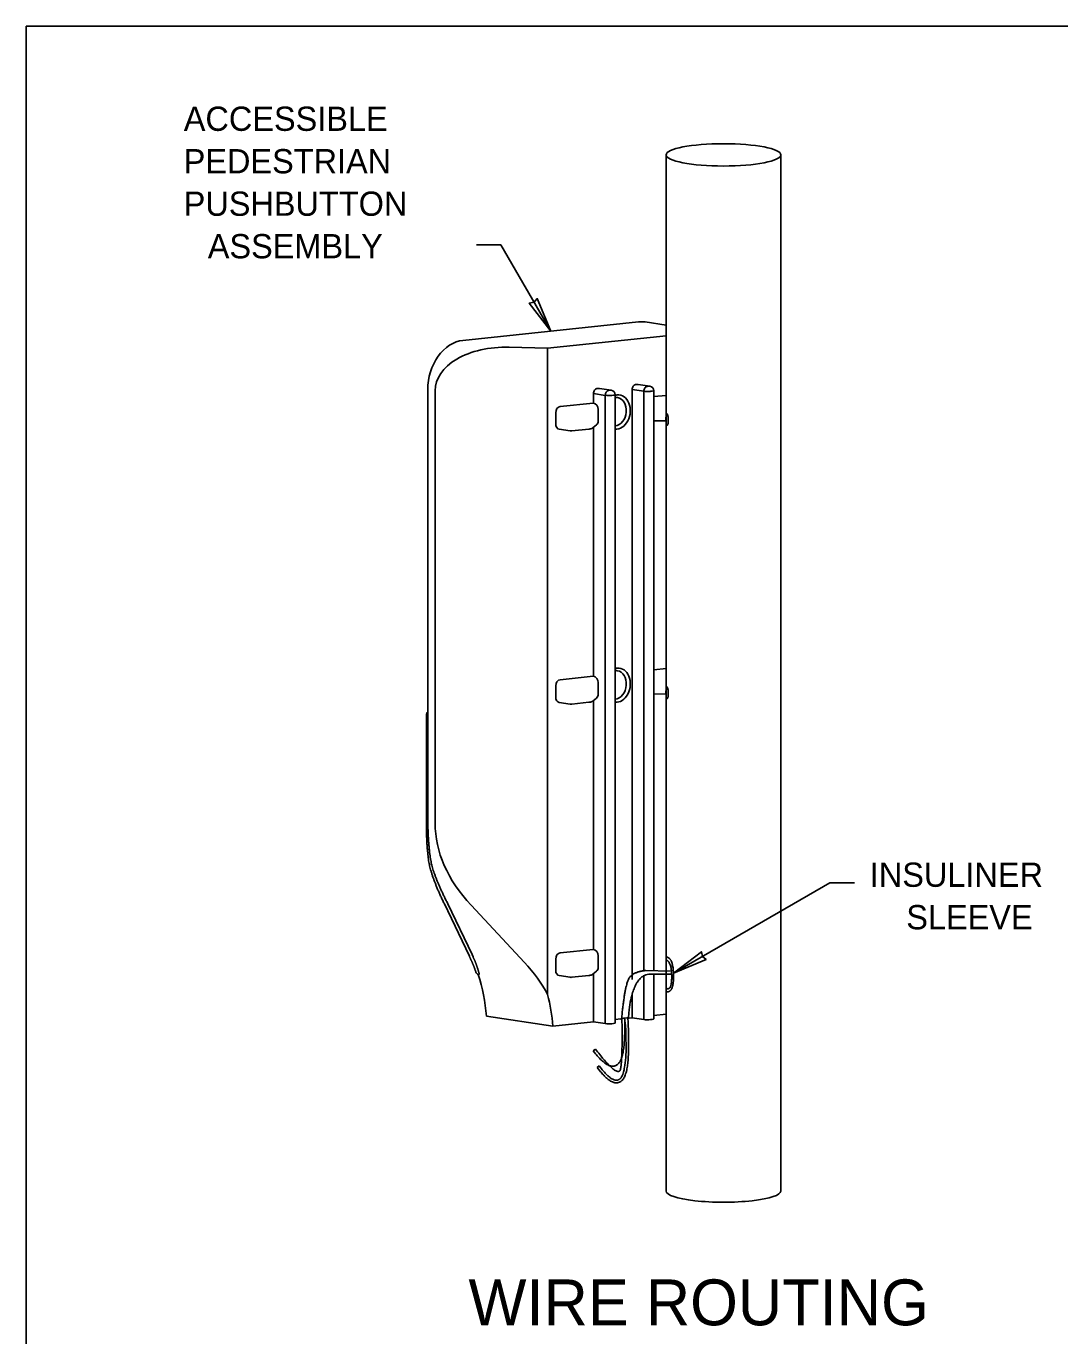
# Model space of a CAD drawing. Extents: x 2815109 to 2818234, y 992846 to 994883.
# Drawn here: x 2815109 to 2815718, y 994113 to 994883 of the extents above; entities that cross this region are included whole.
import ezdxf

# ---------------------------------------------------------------- set-up
doc = ezdxf.new("R2010")
doc.units = 0
for name, color, linetype in [('Common-Dimensions', 7, 'Continuous'), ('Common-Notes', 7, 'Continuous'), ('Draft_Named_Boundary', 7, 'Continuous'), ('Level 18', 7, 'Continuous'), ('Level 31', 7, 'Continuous'), ('Level 33', 7, 'Continuous'), ('Level 42', 7, 'Continuous')]:
    doc.layers.add(name, color=color, linetype=linetype)

msp = doc.modelspace()

# ---------------------------------------------------------------- linework, layer by layer
at = {"layer": 'Common-Dimensions'}
for p, q in [((2815374.39, 994754.77), (2815388.79, 994754.77)), ((2815418.04, 994704.1), (2815388.79, 994754.77)), ((2815490.29, 994326.38), (2815582.26, 994379.48)), ((2815596.66, 994379.48), (2815582.26, 994379.48))]:
    msp.add_line(p, q, dxfattribs=at)
for points in [[(2815418.04, 994704.1), (2815405.44, 994720.55), (2815408.24, 994721.07), (2815410.09, 994723.24)], [(2815490.29, 994326.38), (2815509.43, 994334.33), (2815507.26, 994336.18), (2815506.74, 994338.98)]]:
    msp.add_lwpolyline(points, close=True, dxfattribs=at)
at = {"layer": 'Draft_Named_Boundary'}
msp.add_lwpolyline([(2815109.48, 992845.97), (2818234.48, 992845.97), (2818234.48, 994883.47), (2815109.48, 994883.47)], close=True, dxfattribs=at)
at = {"layer": 'Level 18'}
for p, q in [((2815474.03, 994327.88), (2815488.4, 994327.61)), ((2815475.73, 994325.67), (2815488.52, 994325.67)), ((2815444.4, 994281.62), (2815443.11, 994280.63)), ((2815446.55, 994271.79), (2815445.35, 994270.87))]:
    msp.add_line(p, q, dxfattribs=at)
msp.add_ellipse((2815461.77, 994299.66), major_axis=(-2.42, -0.31), ratio=0.103975, start_param=2.35204, end_param=6.98667, dxfattribs=at)
for points, degree in [([(2815459.75, 994299.54), (2815461.29, 994315.63), (2815465.2, 994327.28), (2815474.03, 994327.88)], 2), ([(2815463.71, 994300.06), (2815464.04, 994304.36), (2815464.51, 994307.63), (2815465.79, 994313.65), (2815466.62, 994316.35), (2815468.13, 994319.67), (2815468.68, 994320.66), (2815469.86, 994322.36), (2815470.49, 994323.08), (2815471.82, 994324.25), (2815472.53, 994324.71), (2815474.03, 994325.38), (2815474.84, 994325.59), (2815475.73, 994325.67)], 3), ([(2815443.11, 994280.63), (2815444.25, 994279.14), (2815445.32, 994277.84), (2815447.35, 994275.62), (2815448.3, 994274.7), (2815450.12, 994273.21), (2815450.99, 994272.63), (2815452.3, 994272.02), (2815452.73, 994271.86), (2815453.61, 994271.65), (2815454.05, 994271.59), (2815454.94, 994271.6), (2815455.38, 994271.67), (2815456.22, 994271.93), (2815456.61, 994272.12), (2815457.33, 994272.6), (2815457.65, 994272.89), (2815458.23, 994273.52), (2815458.49, 994273.87), (2815459.19, 994275), (2815459.56, 994275.86), (2815460.19, 994277.78), (2815460.44, 994278.85), (2815461.08, 994282.36), (2815461.34, 994285.11), (2815461.61, 994291.33), (2815461.63, 994294.79), (2815461.56, 994298.81), (2815461.56, 994299.1), (2815461.55, 994299.38)], 3), ([(2815444.4, 994281.62), (2815457.92, 994263.9), (2815460.34, 994276.37), (2815459.94, 994299.59)], 2), ([(2815445.35, 994270.87), (2815446.5, 994269.38), (2815447.57, 994268.08), (2815449.59, 994265.86), (2815450.54, 994264.94), (2815452.37, 994263.45), (2815453.24, 994262.87), (2815454.54, 994262.26), (2815454.98, 994262.1), (2815455.86, 994261.89), (2815456.3, 994261.83), (2815457.19, 994261.84), (2815457.63, 994261.91), (2815458.46, 994262.17), (2815458.86, 994262.36), (2815459.58, 994262.84), (2815459.9, 994263.12), (2815460.48, 994263.76), (2815460.74, 994264.11), (2815461.44, 994265.24), (2815461.81, 994266.1), (2815462.44, 994268.02), (2815462.69, 994269.09), (2815463.33, 994272.59), (2815463.58, 994275.35), (2815463.86, 994281.57), (2815463.87, 994285.03), (2815463.76, 994292.17), (2815463.64, 994295.8), (2815463.48, 994300.06)], 3), ([(2815446.55, 994271.79), (2815447.68, 994270.32), (2815448.72, 994269.06), (2815450.67, 994266.92), (2815451.57, 994266.05), (2815453.26, 994264.67), (2815454.03, 994264.17), (2815455.1, 994263.67), (2815455.45, 994263.54), (2815456.11, 994263.38), (2815456.43, 994263.34), (2815457.03, 994263.35), (2815457.32, 994263.4), (2815457.87, 994263.57), (2815458.13, 994263.69), (2815458.62, 994264.02), (2815458.86, 994264.22), (2815459.29, 994264.7), (2815459.49, 994264.97), (2815460.07, 994265.9), (2815460.4, 994266.65), (2815460.97, 994268.41), (2815461.21, 994269.41), (2815462.23, 994275), (2815462.42, 994281.31), (2815462.25, 994291.86), (2815462.15, 994295.17), (2815461.48, 994299.88)], 3)]:
    msp.add_open_spline(points, degree=degree, dxfattribs=at)
at = {"layer": 'Level 31'}
for p, q in [((2815485.92, 994807.77), (2815485.92, 994295.55)), ((2815553.42, 994198.16), (2815553.42, 994807.77)), ((2815485.92, 994334.09), (2815486.22, 994334.04)), ((2815485.92, 994295.55), (2815485.92, 994198.16))]:
    msp.add_line(p, q, dxfattribs=at)
msp.add_ellipse((2815519.67, 994807.77), major_axis=(-33.75, 0), ratio=0.194841, dxfattribs=at)
for centre, major_axis, ratio, start_param, end_param in [((2815486.32, 994325.61), (0.16, -8.44), 0.151332, 2.932249, 3.096468), ((2815486.32, 994325.61), (0.16, -8.44), 0.151332, 6.073842, 6.23806), ((2815519.67, 994198.16), (-33.75, 0), 0.194841, 6.283185, 9.424778)]:
    msp.add_ellipse(centre, major_axis=major_axis, ratio=ratio, start_param=start_param, end_param=end_param, dxfattribs=at)
for points, degree in [([(2815486.32, 994648.67), (2815485.85, 994648.93), (2815485.85, 994655.73), (2815486.25, 994655.47)], 2), ([(2815486.25, 994655.47), (2815486.99, 994655.75), (2815487.37, 994648.82), (2815486.44, 994648.66)], 2), ([(2815486.32, 994487.95), (2815485.85, 994488.21), (2815485.85, 994495.01), (2815486.25, 994494.75)], 2), ([(2815486.25, 994494.75), (2815486.99, 994495.03), (2815487.37, 994488.1), (2815486.44, 994487.94)], 2), ([(2815485.92, 994336.11), (2815487.55, 994335.3), (2815487.72, 994335.18), (2815488.04, 994334.89), (2815488.19, 994334.72), (2815488.59, 994334.21), (2815488.79, 994333.86), (2815489.13, 994333.11), (2815489.28, 994332.71), (2815489.53, 994331.87), (2815489.64, 994331.43), (2815489.93, 994330.05), (2815490.08, 994329.04), (2815490.27, 994326.95), (2815490.33, 994325.87), (2815490.34, 994323.72), (2815490.31, 994322.67), (2815490.14, 994320.68), (2815490.01, 994319.75), (2815489.71, 994318.5), (2815489.6, 994318.11), (2815489.31, 994317.35), (2815489.14, 994316.99), (2815488.78, 994316.47), (2815488.64, 994316.29), (2815488.3, 994315.96), (2815488.1, 994315.8), (2815487.61, 994315.53), (2815487.32, 994315.43), (2815486.72, 994315.34), (2815486.4, 994315.35), (2815486.12, 994315.41)], 3), ([(2815486.43, 994333.87), (2815489.13, 994332.51), (2815489.32, 994316.56), (2815486.5, 994317.17)], 2), ([(2815486.22, 994317.35), (2815486.02, 994317.77), (2815485.89, 994318.42), (2815485.92, 994319.67)], 2)]:
    msp.add_open_spline(points, degree=degree, dxfattribs=at)
at = {"layer": 'Level 33'}
for p, q in [((2815469.7, 994709.55), (2815366.38, 994698.65)), ((2815485.92, 994707.65), (2815473.68, 994709.47)), ((2815485.92, 994701.31), (2815416.23, 994693.96)), ((2815393.59, 994694.6), (2815416.23, 994693.96)), ((2815416.23, 994693.96), (2815416.23, 994313.73)), ((2815446.29, 994670.34), (2815445.26, 994670.23)), ((2815453.64, 994669.3), (2815446.69, 994670.33)), ((2815469.02, 994672.74), (2815467.99, 994672.63)), ((2815476.37, 994671.69), (2815469.42, 994672.73)), ((2815345.72, 994669.69), (2815345.72, 994477.71)), ((2815350.06, 994414.57), (2815350.06, 994669.04)), ((2815443.19, 994667.34), (2815443.19, 994661.79)), ((2815455.95, 994299.04), (2815455.95, 994666.63)), ((2815465.92, 994669.73), (2815465.92, 994416.82)), ((2815478.68, 994327.79), (2815478.68, 994669.02)), ((2815478.68, 994665.54), (2815485.92, 994666.3)), ((2815420.98, 994649.41), (2815420.98, 994656.1)), ((2815443.02, 994661.78), (2815423.56, 994659.72)), ((2815445.95, 994658.04), (2815445.95, 994651.34)), ((2815442.94, 994647.34), (2815444.89, 994648.9)), ((2815443.19, 994647.55), (2815443.19, 994501.07)), ((2815478.68, 994651.32), (2815485.92, 994651.3)), ((2815423.07, 994646.34), (2815429.58, 994645.37)), ((2815430.43, 994645.35), (2815440.51, 994646.41)), ((2815443.02, 994501.05), (2815423.56, 994499)), ((2815478.68, 994504.82), (2815485.92, 994505.58)), ((2815420.98, 994488.69), (2815420.98, 994495.38)), ((2815445.95, 994497.31), (2815445.95, 994490.62)), ((2815423.07, 994485.62), (2815429.58, 994484.65)), ((2815430.43, 994484.63), (2815440.51, 994485.69)), ((2815442.94, 994486.62), (2815444.89, 994488.18)), ((2815443.19, 994486.83), (2815443.19, 994340.35)), ((2815478.68, 994490.6), (2815485.92, 994490.58)), ((2815344.93, 994477.98), (2815344.93, 994415.49)), ((2815345.72, 994477.71), (2815345.72, 994415.21)), ((2815465.92, 994416.82), (2815465.92, 994322.72)), ((2815355.29, 994367.45), (2815370.2, 994336.26)), ((2815357.52, 994367.07), (2815356.84, 994368.47)), ((2815371.76, 994337.28), (2815357.52, 994367.07)), ((2815402.6, 994332.68), (2815371.2, 994366.33)), ((2815443.02, 994340.33), (2815423.56, 994338.28)), ((2815372.4, 994335.88), (2815371.76, 994337.28)), ((2815420.98, 994327.96), (2815420.98, 994334.66)), ((2815445.95, 994336.59), (2815445.95, 994329.9)), ((2815423.07, 994324.9), (2815429.58, 994323.93)), ((2815430.43, 994323.91), (2815440.51, 994324.97)), ((2815442.94, 994325.9), (2815444.89, 994327.46)), ((2815443.19, 994326.11), (2815443.19, 994297.7)), ((2815478.68, 994301.44), (2815478.68, 994325.67)), ((2815465.92, 994313.8), (2815465.92, 994300.1)), ((2815380.26, 994301.02), (2815419.36, 994295.18)), ((2815478.68, 994301.44), (2815485.92, 994302.2)), ((2815478.68, 994299.39), (2815478.68, 994301.44)), ((2815419.36, 994295.18), (2815443.19, 994297.7)), ((2815450.15, 994296.66), (2815443.19, 994297.7)), ((2815454.98, 994296.73), (2815453.95, 994296.62)), ((2815455.95, 994299.04), (2815459.35, 994299.4)), ((2815455.95, 994296.99), (2815455.95, 994299.04)), ((2815464.14, 994299.91), (2815465.92, 994300.1)), ((2815472.88, 994299.06), (2815465.92, 994300.1)), ((2815477.71, 994299.13), (2815476.68, 994299.02))]:
    msp.add_line(p, q, dxfattribs=at)
for points in [[(2815455.95, 994664.97), (2815456.12, 994665), (2815456.23, 994665.01)], [(2815455.95, 994504.25), (2815456.12, 994504.28), (2815456.23, 994504.29)]]:
    msp.add_lwpolyline(points, dxfattribs=at)
for centre, radius, start, end in [((2815475.98, 994669.02), 2.7, 0, 81.51737), ((2815453.25, 994666.63), 2.7, 0, 81.51737), ((2815430.08, 994648.71), 3.37, 261.51737, 276.02174), ((2815348.3, 994477.98), 3.37, 139.93574, 180), ((2815430.08, 994487.99), 3.37, 261.51737, 276.02174), ((2815376.69, 994328.15), 2.92, 202.95642, 243.4546), ((2815430.08, 994327.26), 3.37, 261.51737, 276.02174)]:
    msp.add_arc(centre, radius, start, end, dxfattribs=at)
for centre, major_axis, ratio, start_param, end_param in [((2815469.7, 994682.77), (3.98, 26.7), 0.759279, 0, 0.193955), ((2815366.38, 994671.87), (3.98, 26.7), 0.759279, 0.193955, 1.764752), ((2815393.59, 994667.81), (43.51, -1.98), 0.614587, 1.598727, 3.169524), ((2815446.29, 994667.66), (0.4, 2.67), 0.759279, 0, 0.193955), ((2815467.99, 994669.95), (0.4, 2.67), 0.759279, 0.193955, 1.764752), ((2815469.02, 994670.06), (0.4, 2.67), 0.759279, 0, 0.193955), ((2815445.26, 994667.55), (0.4, 2.67), 0.759279, 0.193955, 1.764752), ((2815457.14, 994656.49), (-1.49, -10.01), 0.759279, 0.038851, 3.335548), ((2815457.14, 994656.49), (-1.49, -10.01), 0.759279, 3.335548, 3.490652), ((2815456.06, 994656.65), (1.24, 8.35), 0.759279, 3.31837, 6.29201), ((2815423.56, 994656.37), (-0.5, -3.34), 0.759279, 3.335548, 4.906344), ((2815443.02, 994658.43), (3.78, 1.32), 0.820766, 1.246381, 1.291135), ((2815443.07, 994658.46), (1.14, -3.25), 0.815203, 1.165356, 2.691399), ((2815423.56, 994649.68), (-0.5, -3.34), 0.759279, 4.906344, 6.283185), ((2815443.07, 994651.77), (-1.14, 3.25), 0.815203, 3.421254, 4.306949), ((2815443.02, 994497.71), (3.78, 1.32), 0.820766, 1.246381, 1.291135), ((2815443.07, 994497.74), (1.14, -3.25), 0.815203, 1.165356, 2.691399), ((2815457.14, 994495.76), (-1.49, -10.01), 0.759279, 0.038851, 3.335548), ((2815457.14, 994495.76), (-1.49, -10.01), 0.759279, 3.335548, 3.490652), ((2815456.06, 994495.93), (1.24, 8.35), 0.759279, 3.31837, 6.29201), ((2815423.56, 994495.65), (-0.5, -3.34), 0.759279, 3.335548, 4.906344), ((2815423.56, 994488.96), (-0.5, -3.34), 0.759279, 4.906344, 6.283185), ((2815443.07, 994491.05), (-1.14, 3.25), 0.815203, 3.421254, 4.306949), ((2815502.41, 994410.26), (-152.29, 6.92), 0.614587, 0.027931, 0.56094), ((2815443.02, 994336.99), (3.78, 1.32), 0.820766, 1.246381, 1.291135), ((2815443.07, 994337.02), (1.14, -3.25), 0.815203, 1.165356, 2.691399), ((2815271.38, 994288.75), (-152.29, 6.92), 0.614587, 3.484746, 3.702533), ((2815423.56, 994334.93), (-0.5, -3.34), 0.759279, 3.335548, 4.906344), ((2815308.37, 994283.24), (-13.94, -93.47), 0.759279, 1.873697, 2.149994), ((2815423.56, 994328.24), (-0.5, -3.34), 0.759279, 4.906344, 6.283185), ((2815443.07, 994330.33), (-1.14, 3.25), 0.815203, 3.421254, 4.306949), ((2815347.47, 994277.41), (-13.94, -93.47), 0.759279, 1.873697, 2.079974), ((2815452.21, 994296.88), (-2.7, 0), 0.12543, 0.699253, 2.27005), ((2815453.25, 994296.99), (-2.7, 0), 0.12543, 2.27005, 3.141593), ((2815474.94, 994299.28), (-2.7, 0), 0.12543, 0.699253, 2.27005), ((2815475.98, 994299.39), (-2.7, 0), 0.12543, 2.27005, 3.141593)]:
    msp.add_ellipse(centre, major_axis=major_axis, ratio=ratio, start_param=start_param, end_param=end_param, dxfattribs=at)
for points in [[(2815456.23, 994665.01), (2815456.58, 994665.06), (2815456.92, 994665.04), (2815457.25, 994665)], [(2815442.94, 994647.34), (2815442.1, 994646.67), (2815441.29, 994646.55), (2815440.51, 994646.42)], [(2815456.23, 994504.29), (2815456.58, 994504.34), (2815456.92, 994504.32), (2815457.25, 994504.28)], [(2815442.94, 994486.62), (2815442.1, 994485.95), (2815441.29, 994485.83), (2815440.51, 994485.7)], [(2815344.93, 994415.49), (2815344.91, 994398.34), (2815348.51, 994381.58), (2815355.29, 994367.45)], [(2815356.84, 994368.47), (2815349.95, 994382.16), (2815346.08, 994398.5), (2815345.72, 994415.21)], [(2815370.2, 994336.26), (2815371.62, 994333.31), (2815372.89, 994330.21), (2815374.01, 994327.01)], [(2815375.93, 994326.32), (2815374.84, 994329.74), (2815373.74, 994332.9), (2815372.4, 994335.88)], [(2815375.39, 994325.54), (2815375.82, 994325.5), (2815375.99, 994325.77), (2815375.93, 994326.32)], [(2815442.94, 994325.9), (2815442.1, 994325.23), (2815441.29, 994325.11), (2815440.51, 994324.98)]]:
    msp.add_open_spline(points, degree=2, dxfattribs=at)
at = {"layer": 'Level 42'}
for p, q in [((2815475.98, 994671.7), (2815474.94, 994671.59)), ((2815443.19, 994667.34), (2815450.15, 994666.3)), ((2815450.15, 994666.3), (2815450.15, 994296.66)), ((2815453.25, 994669.3), (2815452.21, 994669.2)), ((2815453.95, 994666.26), (2815454.98, 994666.37)), ((2815465.92, 994669.73), (2815472.88, 994668.7)), ((2815472.88, 994668.7), (2815472.88, 994327.73)), ((2815476.68, 994668.66), (2815477.71, 994668.76)), ((2815472.88, 994324.85), (2815472.88, 994299.06))]:
    msp.add_line(p, q, dxfattribs=at)
for centre, major_axis, ratio, start_param, end_param in [((2815474.94, 994668.91), (0.4, 2.67), 0.759279, 0.193955, 1.764752), ((2815475.98, 994669.02), (-0.4, -2.67), 0.759279, 3.141593, 3.335548), ((2815452.21, 994666.52), (0.4, 2.67), 0.759279, 0.193955, 1.764752), ((2815452.21, 994666.52), (-2.7, 0), 0.12543, 0.699253, 2.27005), ((2815453.25, 994666.63), (-0.4, -2.67), 0.759279, 3.141593, 3.335548), ((2815453.25, 994666.63), (-2.7, 0), 0.12543, 2.27005, 3.141593), ((2815474.94, 994668.91), (-2.7, 0), 0.12543, 0.699253, 2.27005), ((2815475.98, 994669.02), (-2.7, 0), 0.12543, 2.27005, 3.141593)]:
    msp.add_ellipse(centre, major_axis=major_axis, ratio=ratio, start_param=start_param, end_param=end_param, dxfattribs=at)

# ---------------------------------------------------------------- texts
at = {"layer": 'Common-Dimensions'}
for s, p in [('ACCESSIBLE', (2815202.18, 994821.89)), ('PEDESTRIAN', (2815202.14, 994796.9)), ('PUSHBUTTON', (2815202.14, 994771.91)), ('ASSEMBLY', (2815216.31, 994746.92)), ('INSULINER', (2815605.76, 994377.14)), ('SLEEVE', (2815627.22, 994352.15))]:
    msp.add_text(s, height=14.28, dxfattribs=at).set_placement(p)
at = {"layer": 'Common-Notes'}
msp.add_text('WIRE ROUTING', height=27, dxfattribs=at).set_placement((2815369.69, 994119.17))

doc.saveas('drawing.dxf')
